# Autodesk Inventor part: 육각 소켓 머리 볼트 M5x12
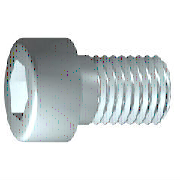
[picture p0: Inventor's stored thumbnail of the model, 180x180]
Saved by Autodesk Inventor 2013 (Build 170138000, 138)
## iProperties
IsCustomPart: 1
Created: 2012-02
Part Number: 육각 소켓 머리 볼트 M5x12
Material: 강철, 연강
Description: 6각 소켓 머리 캡 나사
Document SubType Name: Modeling
Standard: ISO 4762
Designer: mdu-01
Standard Revision: Fourth edition 2004-03-01
Standards Organization: ISO
Language: ko-KR
Size Designation: M5 x 12
Categories: <MemberInstance><Categories><Category DisplayName="조임쇠" InternalName="e4da775c-781d-43d5-af7c-5136215cf5a6" Mnemonic="FSTN"><Category DisplayName="볼트" InternalN
Density: 7.75 g/cm^3
Author: mdu-01
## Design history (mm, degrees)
sketch "스케치1"
  geometry: L1 (-1.167, 0)-(12, 0); L2 (12, 0)-(12, 2.5); L3 (12, 2.5)-(2, 2.5); L4 (2, 2.5)-(1.509, 2.5); L5 (1.509, 2.5)-(0, 2.5); L6 (0, 2.5)-(0, 4.25); L7 (0, 4.25)-(-5, 4.25); L8 (-5, 4.25)-(-5, 2.309); L9 (-5, 2.309)-(-2.5, 2.309); L10 (-2.5, 2.309)-(-1.167, 0); L11 (-8.4, 0)-(15.4, 0) reference; L12 (0, -0.85)-(0, 5.1) reference; L13 (2, 2.5)-(0, 2.5)
  constraints: 22 end point, 6 parallel, 2 collinear, 2 perpendicular, 1 horizontal, 1 point on line
  dimensions: "d1" = 10 distance from line of L3.end L2 (= GEL); "d2" = 0.49086 distance of L4.end L3.end (computed from GAL); "d3" = 5 distance between parallel lines of L8 L6 (= KOH); "d4" = 2.5 distance of L8.end L9.end (= INTI); "d5" = 60 deg angle of L10 L1; "d6" = 5 diameter of L3 L1 (= GD); "d7" = 5 diameter of L5 L1 (= BDM); "d8" = 4.6188 diameter of L9 L1 (= 1.1547 x SW); "d9" = 8.5 diameter of L7 L1 (= KOD); "d26" = 12 distance between parallel lines of L12 L2 (= NLG)
revolve "본체" sketch "스케치1" stored, may be unused: angle "d10" = 90 deg
sketch "스케치2"
  geometry: L1 (0, -5.95)-(0, 5.95) reference; L2 (-5.95, 0)-(5.95, 0) reference; L3 (2.309, 0)-(1.155, -2); L4 (1.155, -2)-(-1.155, -2); L5 (-1.155, -2)-(-2.309, 0); L6 (-2.309, 0)-(-1.155, 2); L7 (-1.155, 2)-(1.155, 2); L8 (1.155, 2)-(2.309, 0); 2 further points
  constraints: 12 end point, 1 coincident, 1 horizontal alignment, 1 point on line, 12 other
extrude "슬롯" join sketch "스케치2" stored distance "d11" = 10; taper "d12" = 0 deg
workplane "Work Plane1"
fillet "Fillet2" dims "d30" = 0.1 (= R)
body "Solid1"
fillet "모깎기1" dims "d17" = 0.5 (= RR)
feature "스레드" dims "d13" = 10 (= GEL), "d14" = 0
chamfer "모따기1" distance "d15" = 0.49076 (= -0.5 x SPD + 0.5 x GD); stored, may be unused: second distance "d16" = 0.49076 (= GUL), angle "d27" = 45 deg
other parameters: "GD" = 5 [user parameter; used in 2 equation terms], "NLG" = 12 [user parameter; used in 1 equation term], "GEL" = 10 [user parameter; used in 2 equation terms], "KOD" = 8.5 [user parameter; used in 1 equation term], "KOH" = 5 [user parameter; used in 1 equation term], "INTI" = 2.5 [user parameter; used in 1 equation term], "GAL" = 0.49076 (= 0.61345 x PTC) [user parameter; used in 1 equation term], "GUL" = 0.49076 (= 0.61345 x PTC) [user parameter; used in 1 equation term], "BDM" = 5 (= NND) [user parameter; used in 1 equation term], "SW" = 4 [user parameter; used in 2 equation terms], "RR" = 0.5 [user parameter; used in 1 equation term], "SPD" = 4.01848 (= NND - 1.2269 x PTC) [user parameter; used in 1 equation term], "d19" = 0, "d28" = 0, "d29" = 0, "R" = 0.1 [user parameter; used in 1 equation term], "TOA" = 30 deg [user parameter], "GD1" = 4.01848 (= THREADDIA - 1.2269 x PTC) [user parameter], "THREADDIA" = 5 [user parameter; used in 1 equation term], "FAWI" = 45 deg [user parameter], "TPU" = 12.5 (computed from PTC) [user parameter], "PTC" = 0.8 [user parameter; used in 5 equation terms], "NND" = 5 [user parameter; used in 2 equation terms], "E0" = 4.62 (= 1.155 x SW) [user parameter]
